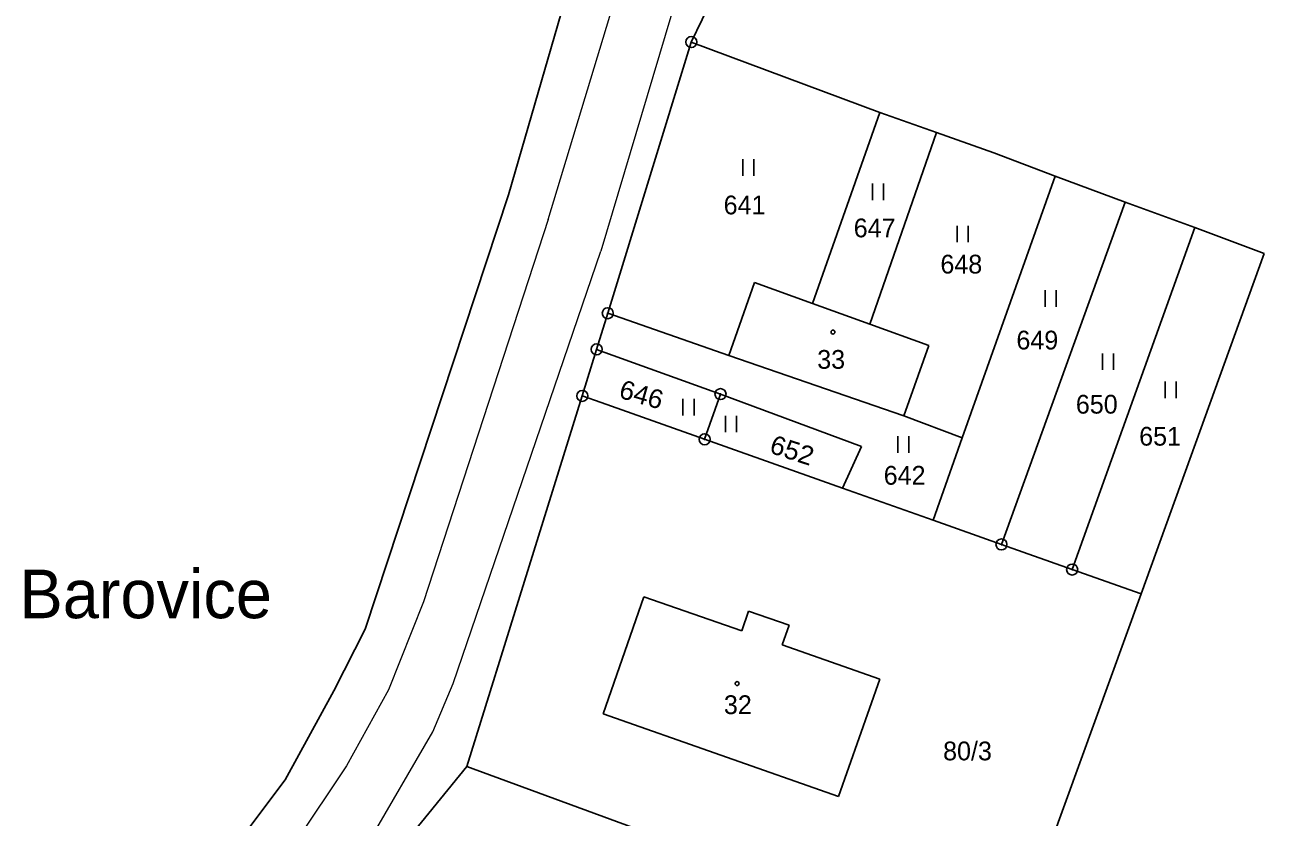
# Model space of a CAD drawing. Extents: x -653193 to -651624, y -1092017 to -1090260.
# Drawn here: x -652809 to -652696.7, y -1091187.1 to -1091115.4 of the extents above; entities that cross this region are included whole.
import ezdxf
from ezdxf.enums import TextEntityAlignment as Align

# ---------------------------------------------------------------- set-up
doc = ezdxf.new("R2010")
doc.units = 0
doc.header["$LTSCALE"] = 0.68
for name, color, linetype, lineweight in [('1', 7, 'Continuous', 25), ('3', 7, 'Continuous', 25), ('4', 7, 'Continuous', 13), ('5', 7, 'Continuous', 25), ('7', 7, 'Continuous', 13), ('8', 7, 'Continuous', 25)]:
    doc.layers.add(name, color=color, linetype=linetype, lineweight=lineweight)
doc.layers.add('2', color=7, linetype='Continuous')

msp = doc.modelspace()

# ---------------------------------------------------------------- linework, layer by layer
at = {"layer": '1'}
for p, q in [((-652744.81, -1091109), (-652748.62, -1091116.93)), ((-652765.2, -1091130.77), (-652760.41, -1091114.3)), ((-652756.19, -1091141.49), (-652748.62, -1091116.93)), ((-652748.62, -1091116.93), (-652731.52, -1091123.31)), ((-652737.62, -1091140.6), (-652731.52, -1091123.31)), ((-652731.52, -1091123.31), (-652726.38, -1091125.11)), ((-652726.38, -1091125.11), (-652732.44, -1091142.48)), ((-652726.38, -1091125.11), (-652721.18, -1091126.96)), ((-652721.18, -1091126.96), (-652715.62, -1091129.08)), ((-652715.62, -1091129.08), (-652724.05, -1091152.78)), ((-652715.62, -1091129.08), (-652709.29, -1091131.43)), ((-652778.19, -1091170.12), (-652765.2, -1091130.77)), ((-652720.5, -1091162.44), (-652709.29, -1091131.43)), ((-652709.29, -1091131.43), (-652702.96, -1091133.73)), ((-652714.09, -1091164.71), (-652702.96, -1091133.73)), ((-652702.96, -1091133.73), (-652696.68, -1091136.09)), ((-652696.68, -1091136.09), (-652707.84, -1091166.92)), ((-652742.89, -1091138.7), (-652745.22, -1091145.32)), ((-652737.62, -1091140.6), (-652742.89, -1091138.7)), ((-652757.2, -1091144.77), (-652756.19, -1091141.49)), ((-652745.22, -1091145.32), (-652756.19, -1091141.49)), ((-652732.44, -1091142.48), (-652737.62, -1091140.6)), ((-652732.44, -1091142.48), (-652727.09, -1091144.41)), ((-652758.5, -1091148.98), (-652757.2, -1091144.77)), ((-652757.2, -1091144.77), (-652745.97, -1091148.82)), ((-652727.09, -1091144.41), (-652729.34, -1091150.8)), ((-652729.34, -1091150.8), (-652745.22, -1091145.32)), ((-652758.5, -1091148.98), (-652768.98, -1091182.55)), ((-652756.8, -1091149.58), (-652758.5, -1091148.98)), ((-652745.97, -1091148.82), (-652747.41, -1091152.91)), ((-652733.19, -1091153.55), (-652745.97, -1091148.82)), ((-652747.41, -1091152.91), (-652756.8, -1091149.58)), ((-652724.05, -1091152.78), (-652729.34, -1091150.8)), ((-652724.05, -1091152.78), (-652726.68, -1091160.25)), ((-652747.41, -1091152.91), (-652734.91, -1091157.33)), ((-652734.91, -1091157.33), (-652733.19, -1091153.55)), ((-652734.91, -1091157.33), (-652726.68, -1091160.25)), ((-652726.68, -1091160.25), (-652720.5, -1091162.44)), ((-652720.5, -1091162.44), (-652714.09, -1091164.71)), ((-652714.09, -1091164.71), (-652707.84, -1091166.92)), ((-652756.61, -1091177.78), (-652752.92, -1091167.18)), ((-652752.92, -1091167.18), (-652744.05, -1091170.26)), ((-652718.72, -1091196.81), (-652707.84, -1091166.92)), ((-652744.05, -1091170.26), (-652743.43, -1091168.47)), ((-652743.43, -1091168.47), (-652739.76, -1091169.75)), ((-652781.02, -1091175.7), (-652778.19, -1091170.12)), ((-652739.76, -1091169.75), (-652740.38, -1091171.54)), ((-652740.38, -1091171.54), (-652731.52, -1091174.63)), ((-652731.52, -1091174.63), (-652735.27, -1091185.28)), ((-652785.43, -1091183.77), (-652781.02, -1091175.7)), ((-652735.27, -1091185.28), (-652756.61, -1091177.78)), ((-652778.83, -1091194.62), (-652768.98, -1091182.55)), ((-652720.05, -1091200.47), (-652768.98, -1091182.55)), ((-652791.06, -1091191.22), (-652785.43, -1091183.77))]:
    msp.add_line(p, q, dxfattribs=at)
at = {"layer": '3'}
for p, q in [((-652743.961, -1091129.04), (-652743.961, -1091127.54)), ((-652742.96, -1091129.04), (-652742.96, -1091127.54)), ((-652732.181, -1091131.24), (-652732.181, -1091129.74)), ((-652731.18, -1091131.24), (-652731.18, -1091129.74)), ((-652724.511, -1091135.07), (-652724.511, -1091133.57)), ((-652723.51, -1091135.07), (-652723.51, -1091133.57)), ((-652716.531, -1091140.91), (-652716.531, -1091139.41)), ((-652715.53, -1091140.91), (-652715.53, -1091139.41)), ((-652711.331, -1091146.63), (-652711.331, -1091145.13)), ((-652710.33, -1091146.63), (-652710.33, -1091145.13)), ((-652705.661, -1091149.19), (-652705.661, -1091147.69)), ((-652704.66, -1091149.19), (-652704.66, -1091147.69)), ((-652749.371, -1091150.76), (-652749.371, -1091149.26)), ((-652748.37, -1091150.76), (-652748.37, -1091149.26)), ((-652745.521, -1091152.28), (-652745.521, -1091150.78)), ((-652744.52, -1091152.28), (-652744.52, -1091150.78)), ((-652729.891, -1091154.14), (-652729.891, -1091152.64)), ((-652728.89, -1091154.14), (-652728.89, -1091152.64))]:
    msp.add_line(p, q, dxfattribs=at)
at = {"layer": '4'}
for p, q in [((-652761.59, -1091133.01), (-652738.2, -1091055.88)), ((-652748.48, -1091107.9), (-652756.82, -1091135.86)), ((-652761.59, -1091133.01), (-652772.9, -1091167.64)), ((-652772.9, -1091167.64), (-652776.08, -1091175.61)), ((-652776.08, -1091175.61), (-652779.87, -1091182.48)), ((-652777.88, -1091189.45), (-652772.06, -1091179.4)), ((-652779.87, -1091182.48), (-652784.51, -1091189.41))]:
    msp.add_line(p, q, dxfattribs=at)
msp.add_lwpolyline([(-652772.06, -1091179.4), (-652770.22, -1091175.03), (-652756.82, -1091135.86)], dxfattribs=at)
at = {"layer": '5'}
for centre in [(-652735.7768, -1091143.1992), (-652744.4668, -1091175.0392)]:
    msp.add_circle(centre, 0.175, dxfattribs=at)
at = {"layer": '8'}
for centre, radius in [((-652748.62, -1091116.9299), 0.5), ((-652748.62, -1091116.9299), 0.0303), ((-652756.19, -1091141.4899), 0.5), ((-652756.19, -1091141.4899), 0.0303), ((-652757.2, -1091144.7699), 0.5), ((-652757.2, -1091144.7699), 0.0303), ((-652745.97, -1091148.8199), 0.5), ((-652758.5, -1091148.9799), 0.5), ((-652758.5, -1091148.9799), 0.0303), ((-652745.97, -1091148.8199), 0.0303), ((-652747.41, -1091152.9099), 0.5), ((-652747.41, -1091152.9099), 0.0303), ((-652720.5, -1091162.4399), 0.5), ((-652720.5, -1091162.4399), 0.0303), ((-652714.09, -1091164.7099), 0.5), ((-652714.09, -1091164.7099), 0.0303)]:
    msp.add_circle(centre, radius, dxfattribs=at)

# ---------------------------------------------------------------- texts
at = {"layer": '2'}
for s, p in [('641', (-652743.789, -1091132.535)), ('647', (-652731.999, -1091134.615)), ('648', (-652724.139, -1091137.895)), ('649', (-652717.249, -1091144.775)), ('33', (-652735.939, -1091146.525)), ('650', (-652711.859, -1091150.585)), ('651', (-652706.119, -1091153.485)), ('642', (-652729.279, -1091157.025)), ('32', (-652744.399, -1091177.805)), ('80/3', (-652723.579, -1091181.995))]:
    msp.add_text(s, height=1.7, dxfattribs=at).set_placement(p, align=Align.CENTER)
at = {"layer": '2', "width": 1.05}
for s, rotation, p in [('646', 344, (-652753.3668, -1091149.6725)), ('652', 342, (-652739.7367, -1091154.7169))]:
    msp.add_text(s, height=1.7, rotation=rotation, dxfattribs=at).set_placement(p, align=Align.CENTER)
at = {"layer": '7'}
msp.add_text('Barovice', height=4.4, dxfattribs=at).set_placement((-652798.079, -1091169.12), align=Align.CENTER)

doc.saveas('drawing.dxf')
